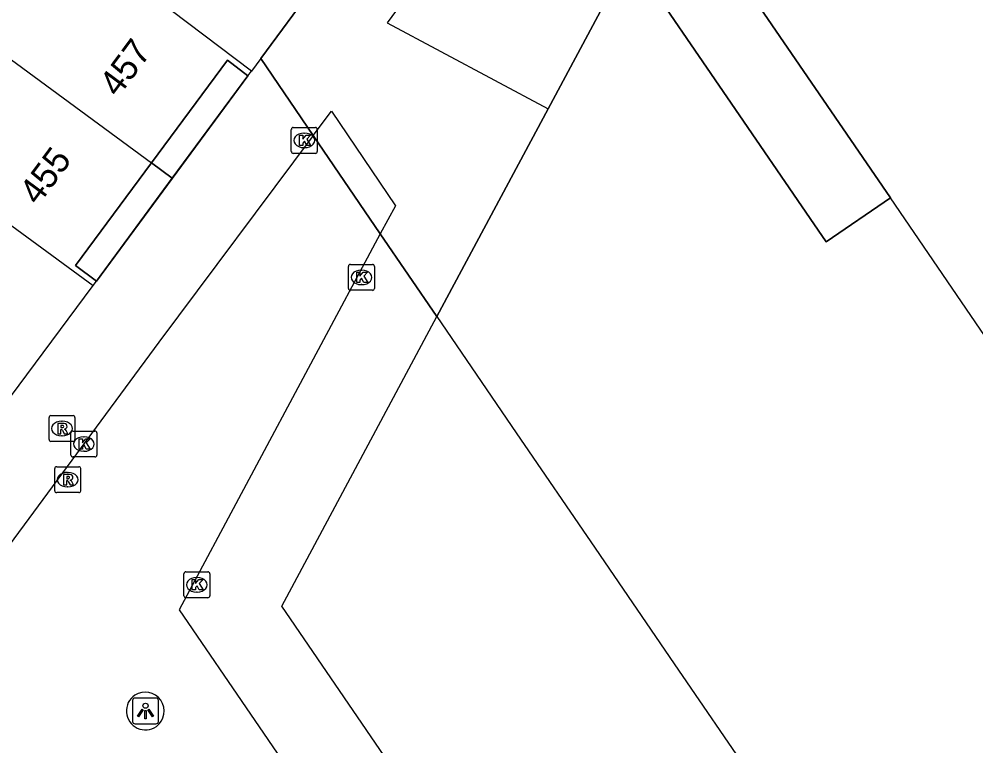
# Model space of a CAD drawing. Extents: x 155275 to 156263, y 382654 to 383635.
# Drawn here: x 155805.74 to 155842.67, y 383296.5 to 383324.56 of the extents above; entities that cross this region are included whole.
import ezdxf

# ---------------------------------------------------------------- set-up
doc = ezdxf.new("R2010")
doc.units = 0
for name, color, linetype in [('IMGEO_Hek', 7, 'Continuous'), ('IMGEO_Kolk', 7, 'Continuous'), ('IMGEO_Lichtpunt', 7, 'Continuous'), ('IMGEO_Pand', 7, 'Continuous'), ('IMGEO_Pand_nummerreeks', 7, 'Continuous'), ('IMGEO_Pand_overbouw', 7, 'Continuous'), ('IMGEO_Rijbaan_lokaal_open', 7, 'Continuous'), ('IMGEO_Rioolput', 7, 'Continuous'), ('IMGEO_Voetpad_open', 7, 'Continuous')]:
    doc.layers.add(name, color=color, linetype=linetype)

msp = doc.modelspace()

# ---------------------------------------------------------------- linework, layer by layer
at = {"layer": 'IMGEO_Hek'}
msp.add_lwpolyline([(155875.206, 383215.094), (155815.878, 383301.895), (155821.855, 383313.072)], dxfattribs=at)
at = {"layer": 'IMGEO_Kolk'}
for p, q in [((155816.242, 383319.449), (155816.242, 383320.301)), ((155816.317, 383320.375), (155817.169, 383320.375)), ((155817.243, 383320.301), (155817.243, 383319.449)), ((155816.73, 383320.155), (155816.755, 383320.155)), ((155816.753, 383319.595), (155816.728, 383319.595)), ((155817.169, 383319.375), (155816.317, 383319.375)), ((155818.446, 383314.16), (155818.446, 383315.012)), ((155818.521, 383315.086), (155819.373, 383315.086)), ((155818.934, 383314.866), (155818.959, 383314.866)), ((155819.447, 383315.012), (155819.447, 383314.16)), ((155819.373, 383314.086), (155818.521, 383314.086)), ((155818.957, 383314.306), (155818.932, 383314.306)), ((155807.734, 383307.726), (155807.734, 383308.578)), ((155807.809, 383308.652), (155808.661, 383308.652)), ((155808.735, 383308.578), (155808.735, 383307.726)), ((155808.222, 383308.432), (155808.247, 383308.432)), ((155808.245, 383307.872), (155808.22, 383307.872)), ((155808.661, 383307.652), (155807.809, 383307.652)), ((155812.095, 383302.292), (155812.095, 383303.144)), ((155812.17, 383303.218), (155813.022, 383303.218)), ((155812.583, 383302.998), (155812.608, 383302.998)), ((155813.096, 383303.144), (155813.096, 383302.292)), ((155813.022, 383302.218), (155812.17, 383302.218)), ((155812.606, 383302.438), (155812.581, 383302.438))]:
    msp.add_line(p, q, dxfattribs=at)
for points in [[(155816.242, 383319.449), (155816.242, 383320.301)], [(155816.317, 383320.375), (155817.169, 383320.375)], [(155817.243, 383320.301), (155817.243, 383319.449)], [(155816.563, 383320.075), (155816.686, 383320.075), (155816.686, 383319.924), (155816.816, 383320.075), (155816.98, 383320.075), (155816.834, 383319.924), (155816.987, 383319.675), (155816.835, 383319.675), (155816.75, 383319.839), (155816.686, 383319.772), (155816.686, 383319.675), (155816.563, 383319.675), (155816.563, 383320.075)], [(155817.169, 383319.375), (155816.317, 383319.375)], [(155818.446, 383314.16), (155818.446, 383315.012)], [(155818.521, 383315.086), (155819.373, 383315.086)], [(155818.767, 383314.786), (155818.89, 383314.786), (155818.89, 383314.635), (155819.02, 383314.786), (155819.184, 383314.786), (155819.038, 383314.635), (155819.191, 383314.386), (155819.039, 383314.386), (155818.954, 383314.55), (155818.89, 383314.483), (155818.89, 383314.386), (155818.767, 383314.386), (155818.767, 383314.786)], [(155819.447, 383315.012), (155819.447, 383314.16)], [(155819.373, 383314.086), (155818.521, 383314.086)], [(155807.734, 383307.726), (155807.734, 383308.578)], [(155807.809, 383308.652), (155808.661, 383308.652)], [(155808.735, 383308.578), (155808.735, 383307.726)], [(155808.055, 383308.352), (155808.178, 383308.352), (155808.178, 383308.201), (155808.308, 383308.352), (155808.472, 383308.352), (155808.326, 383308.201), (155808.479, 383307.952), (155808.327, 383307.952), (155808.242, 383308.116), (155808.178, 383308.049), (155808.178, 383307.952), (155808.055, 383307.952), (155808.055, 383308.352)], [(155808.661, 383307.652), (155807.809, 383307.652)], [(155812.095, 383302.292), (155812.095, 383303.144)], [(155812.17, 383303.218), (155813.022, 383303.218)], [(155813.096, 383303.144), (155813.096, 383302.292)], [(155812.416, 383302.918), (155812.539, 383302.918), (155812.539, 383302.767), (155812.669, 383302.918), (155812.833, 383302.918), (155812.687, 383302.767), (155812.84, 383302.518), (155812.688, 383302.518), (155812.603, 383302.682), (155812.539, 383302.615), (155812.539, 383302.518), (155812.416, 383302.518), (155812.416, 383302.918)], [(155813.022, 383302.218), (155812.17, 383302.218)]]:
    msp.add_lwpolyline(points, dxfattribs=at)
for centre, start, end in [((155816.319, 383320.299), 91.552, 178.448), ((155816.319, 383320.299), 91.552, 178.448), ((155817.167, 383320.299), 1.552, 88.448), ((155817.167, 383320.299), 1.552, 88.448), ((155816.319, 383319.451), 181.552, 268.448), ((155816.319, 383319.451), 181.552, 268.448), ((155817.167, 383319.451), 271.552, 358.448), ((155817.167, 383319.451), 271.552, 358.448), ((155818.523, 383315.01), 91.552, 178.448), ((155818.523, 383315.01), 91.552, 178.448), ((155819.371, 383315.01), 1.552, 88.448), ((155819.371, 383315.01), 1.552, 88.448), ((155818.523, 383314.162), 181.552, 268.448), ((155818.523, 383314.162), 181.552, 268.448), ((155819.371, 383314.162), 271.552, 358.448), ((155819.371, 383314.162), 271.552, 358.448), ((155807.811, 383308.576), 91.552, 178.448), ((155807.811, 383308.576), 91.552, 178.448), ((155808.659, 383308.576), 1.552, 88.448), ((155808.659, 383308.576), 1.552, 88.448), ((155807.811, 383307.728), 181.552, 268.448), ((155807.811, 383307.728), 181.552, 268.448), ((155808.659, 383307.728), 271.552, 358.448), ((155808.659, 383307.728), 271.552, 358.448), ((155812.172, 383303.142), 91.552, 178.448), ((155812.172, 383303.142), 91.552, 178.448), ((155813.02, 383303.142), 1.552, 88.448), ((155813.02, 383303.142), 1.552, 88.448), ((155812.172, 383302.294), 181.552, 268.448), ((155812.172, 383302.294), 181.552, 268.448), ((155813.02, 383302.294), 271.552, 358.448), ((155813.02, 383302.294), 271.552, 358.448)]:
    msp.add_arc(centre, 0.0765, start, end, dxfattribs=at)
for centre, major_axis, ratio, start_param, end_param in [((155816.729, 383319.875), (-0.387, 0.002), 0.722429, 4.712389, 7.853982), ((155816.754, 383319.875), (-0.39, 0.002), 0.717154, 1.570796, 4.712389), ((155818.933, 383314.586), (-0.387, 0.002), 0.722429, 4.712389, 7.853982), ((155818.958, 383314.586), (-0.39, 0.002), 0.717154, 1.570796, 4.712389), ((155808.221, 383308.152), (-0.387, 0.002), 0.722429, 4.712389, 7.853982), ((155808.246, 383308.152), (-0.39, 0.002), 0.717154, 1.570796, 4.712389), ((155812.582, 383302.718), (-0.387, 0.002), 0.722429, 4.712389, 7.853982), ((155812.607, 383302.718), (-0.39, 0.002), 0.717154, 1.570796, 4.712389)]:
    msp.add_ellipse(centre, major_axis=major_axis, ratio=ratio, start_param=start_param, end_param=end_param, dxfattribs=at)
at = {"layer": 'IMGEO_Lichtpunt'}
for p, q in [((155810.116, 383298.25), (155810.116, 383297.443)), ((155810.116, 383298.25), (155810.116, 383297.443)), ((155811.018, 383298.345), (155810.21, 383298.345)), ((155811.018, 383298.345), (155810.21, 383298.345)), ((155811.112, 383297.443), (155811.112, 383298.25)), ((155811.112, 383297.443), (155811.112, 383298.25)), ((155810.21, 383297.349), (155811.018, 383297.349)), ((155810.21, 383297.349), (155811.018, 383297.349))]:
    msp.add_line(p, q, dxfattribs=at)
for points in [[(155810.49, 383297.914), (155810.529, 383297.886), (155810.341, 383297.624), (155810.303, 383297.651), (155810.49, 383297.914)], [(155810.592, 383297.866), (155810.639, 383297.866), (155810.639, 383297.544), (155810.592, 383297.544), (155810.592, 383297.866)], [(155810.702, 383297.886), (155810.74, 383297.913), (155810.927, 383297.651), (155810.888, 383297.623), (155810.702, 383297.886)]]:
    msp.add_lwpolyline(points, dxfattribs=at)
msp.add_circle((155810.615, 383298.048), 0.0994, dxfattribs=at)
for centre, start, end in [((155810.21, 383298.25), 90, 180), ((155810.21, 383298.25), 90, 180), ((155811.018, 383298.25), 0, 90), ((155811.018, 383298.25), 0, 90), ((155810.21, 383297.443), 180, 270), ((155810.21, 383297.443), 180, 270), ((155811.018, 383297.443), 270, 0), ((155811.018, 383297.443), 270, 360)]:
    msp.add_arc(centre, 0.0946, start, end, dxfattribs=at)
at = {"layer": 'IMGEO_Pand'}
for points in [[(155814.704, 383322.549), (155806.716, 383328.599)], [(155815.059, 383323.031), (155819.212, 383328.662)], [(155839.367, 383317.662), (155836.881, 383315.962), (155836.27, 383316.857), (155833.221, 383321.318), (155829.325, 383327.019), (155826.154, 383321.097)], [(155803.581, 383324.349), (155810.843, 383319.005)], [(155810.843, 383319.005), (155813.774, 383322.971), (155814.565, 383322.361)], [(155815.059, 383323.031), (155814.704, 383322.549)], [(155814.565, 383322.361), (155814.704, 383322.549)], [(155826.154, 383321.097), (155821.855, 383313.072)], [(155800.509, 383320.186), (155808.587, 383314.27)], [(155808.716, 383314.444), (155807.912, 383315.039), (155810.843, 383319.005)], [(155858.063, 383290.277), (155856.982, 383291.861), (155853.935, 383296.324), (155850.889, 383300.785), (155847.843, 383305.247), (155844.797, 383309.709), (155841.751, 383314.171), (155839.367, 383317.662)], [(155808.587, 383314.27), (155808.716, 383314.444)], [(155805.407, 383309.97), (155808.587, 383314.27)], [(155821.855, 383313.072), (155824.923, 383308.587), (155827.973, 383304.128), (155831.023, 383299.669), (155834.073, 383295.21), (155837.123, 383290.751), (155840.173, 383286.292), (155843.223, 383281.833), (155846.273, 383277.374), (155847.799, 383275.144), (155850.849, 383270.685), (155853.899, 383266.226), (155856.949, 383261.767), (155859.999, 383257.308), (155863.049, 383252.849), (155866.099, 383248.39), (155869.149, 383243.931), (155872.199, 383239.472), (155875.249, 383235.013), (155878.299, 383230.554), (155881.349, 383226.094), (155884.399, 383221.636), (155887.087, 383217.706)]]:
    msp.add_lwpolyline(points, dxfattribs=at)
at = {"layer": 'IMGEO_Pand_overbouw'}
for points in [[(155821.855, 383313.072), (155826.154, 383321.097), (155829.325, 383327.019), (155833.221, 383321.318), (155836.27, 383316.857), (155836.881, 383315.962), (155839.367, 383317.662), (155833.414, 383326.361), (155825.752, 383337.528), (155823.869, 383334.975), (155822.317, 383332.871), (155819.212, 383328.662), (155815.059, 383323.031), (155817.087, 383320.059), (155819.677, 383316.264)], [(155810.843, 383319.005), (155811.648, 383318.413), (155814.565, 383322.361), (155813.774, 383322.971)], [(155808.716, 383314.444), (155811.648, 383318.413), (155810.843, 383319.005), (155807.912, 383315.039)]]:
    msp.add_lwpolyline(points, close=True, dxfattribs=at)
at = {"layer": 'IMGEO_Rijbaan_lokaal_open'}
for points in [[(155817.087, 383320.059), (155817.796, 383321.009), (155820.258, 383317.35), (155819.677, 383316.264)], [(155817.087, 383320.059), (155811.131, 383312.082), (155798.256, 383294.644), (155789.533, 383282.828), (155777.762, 383266.885), (155770.477, 383257.018), (155750.942, 383230.559), (155753.136, 383227.355), (155767.095, 383206.967), (155771.224, 383200.936), (155773.915, 383197.049), (155790.895, 383199.943), (155792.328, 383200.159), (155792.43, 383196.787)], [(155819.677, 383316.264), (155817.087, 383320.059)], [(155819.677, 383316.264), (155811.913, 383301.75), (155829.44, 383276.11), (155849.638, 383246.563), (155871.364, 383214.781)]]:
    msp.add_lwpolyline(points, dxfattribs=at)
for centre, start, end in [((155810.599, 383297.84), 306.1685, 122.9651), ((155810.61, 383297.847), 124.0068, 305.1268)]:
    msp.add_arc(centre, 0.734, start, end, dxfattribs=at)
at = {"layer": 'IMGEO_Rioolput'}
for p, q in [((155806.963, 383309.25), (155807.815, 383309.25)), ((155806.888, 383308.324), (155806.888, 383309.176)), ((155807.376, 383309.03), (155807.401, 383309.03)), ((155807.889, 383309.176), (155807.889, 383308.324)), ((155807.399, 383308.47), (155807.374, 383308.47)), ((155807.815, 383308.25), (155806.963, 383308.25)), ((155807.109, 383306.35), (155807.109, 383307.202)), ((155807.184, 383307.276), (155808.036, 383307.276)), ((155807.597, 383307.056), (155807.622, 383307.056)), ((155808.11, 383307.202), (155808.11, 383306.35)), ((155808.036, 383306.276), (155807.184, 383306.276)), ((155807.62, 383306.496), (155807.595, 383306.496))]:
    msp.add_line(p, q, dxfattribs=at)
for points in [[(155806.963, 383309.25), (155807.815, 383309.25)], [(155806.888, 383308.324), (155806.888, 383309.176)], [(155807.477, 383308.948), (155807.225, 383308.95), (155807.225, 383308.55)], [(155807.403, 383308.869), (155807.349, 383308.869), (155807.349, 383308.788)], [(155807.889, 383309.176), (155807.889, 383308.324)], [(155807.225, 383308.55), (155807.349, 383308.55), (155807.349, 383308.712), (155807.36, 383308.712)], [(155807.349, 383308.788), (155807.401, 383308.788)], [(155807.407, 383308.683), (155807.478, 383308.55), (155807.618, 383308.55), (155807.553, 383308.676)], [(155807.815, 383308.25), (155806.963, 383308.25)], [(155807.109, 383306.35), (155807.109, 383307.202)], [(155807.184, 383307.276), (155808.036, 383307.276)], [(155808.11, 383307.202), (155808.11, 383306.35)], [(155807.698, 383306.974), (155807.446, 383306.976), (155807.446, 383306.576)], [(155807.446, 383306.576), (155807.57, 383306.576), (155807.57, 383306.738), (155807.581, 383306.738)], [(155807.624, 383306.895), (155807.57, 383306.895), (155807.57, 383306.814)], [(155807.57, 383306.814), (155807.622, 383306.814)], [(155807.628, 383306.709), (155807.699, 383306.576), (155807.839, 383306.576), (155807.774, 383306.702)], [(155808.036, 383306.276), (155807.184, 383306.276)]]:
    msp.add_lwpolyline(points, dxfattribs=at)
for centre, radius, start, end in [((155806.965, 383309.174), 0.0765, 91.552, 178.448), ((155806.965, 383309.174), 0.0765, 91.552, 178.448), ((155807.813, 383309.174), 0.0765, 1.552, 88.448), ((155807.813, 383309.174), 0.0765, 1.552, 88.448), ((155807.409, 383308.773), 0.0964, 77.0061, 93.1865), ((155807.423, 383308.83), 0.0378, 276.6634, 79.6772), ((155807.476, 383308.838), 0.109, 350.3612, 89.416), ((155807.359, 383308.659), 0.0533, 26.0293, 88.6989), ((155807.385, 383308.977), 0.19, 274.7715, 282.9687), ((155807.474, 383308.838), 0.112, 277.5842, 350.9817), ((155807.458, 383308.623), 0.108, 29.5134, 73.7905), ((155806.965, 383308.326), 0.0765, 181.552, 268.448), ((155806.965, 383308.326), 0.0765, 181.552, 268.448), ((155807.813, 383308.326), 0.0765, 271.552, 358.448), ((155807.813, 383308.326), 0.0765, 271.552, 358.448), ((155807.186, 383307.2), 0.0765, 91.552, 178.448), ((155807.186, 383307.2), 0.0765, 91.552, 178.448), ((155808.034, 383307.2), 0.0765, 1.552, 88.448), ((155808.034, 383307.2), 0.0765, 1.552, 88.448), ((155807.58, 383306.685), 0.0533, 26.0293, 88.6989), ((155807.606, 383307.003), 0.19, 274.7715, 282.9687), ((155807.63, 383306.799), 0.0964, 77.0061, 93.1865), ((155807.644, 383306.856), 0.0378, 276.6634, 79.6772), ((155807.697, 383306.864), 0.109, 350.3612, 89.416), ((155807.695, 383306.864), 0.112, 277.5842, 350.9817), ((155807.679, 383306.649), 0.108, 29.5134, 73.7905), ((155807.186, 383306.352), 0.0765, 181.552, 268.448), ((155807.186, 383306.352), 0.0765, 181.552, 268.448), ((155808.034, 383306.352), 0.0765, 271.552, 358.448), ((155808.034, 383306.352), 0.0765, 271.552, 358.448)]:
    msp.add_arc(centre, radius, start, end, dxfattribs=at)
for centre, major_axis, ratio, start_param, end_param in [((155807.375, 383308.75), (-0.387, 0.002), 0.722429, 4.712389, 7.853982), ((155807.4, 383308.75), (-0.39, 0.002), 0.717154, 1.570796, 4.712389), ((155807.596, 383306.776), (-0.387, 0.002), 0.722429, 4.712389, 7.853982), ((155807.621, 383306.776), (-0.39, 0.002), 0.717154, 1.570796, 4.712389)]:
    msp.add_ellipse(centre, major_axis=major_axis, ratio=ratio, start_param=start_param, end_param=end_param, dxfattribs=at)
at = {"layer": 'IMGEO_Voetpad_open'}
for points in [[(155827.631, 383334.79), (155833.414, 383326.361), (155839.367, 383317.662)], [(155827.022, 383334.026), (155819.943, 383324.409), (155826.154, 383321.097)], [(155817.087, 383320.059), (155815.059, 383323.031)], [(155814.565, 383322.361), (155808.716, 383314.444)], [(155821.855, 383313.072), (155819.677, 383316.264)], [(155875.206, 383215.094), (155815.878, 383301.895), (155821.855, 383313.072)]]:
    msp.add_lwpolyline(points, dxfattribs=at)

# ---------------------------------------------------------------- texts
at = {"layer": 'IMGEO_Pand_nummerreeks'}
for s, p in [('457', (155809.556, 383321.502)), ('455', (155806.47, 383317.327))]:
    msp.add_text(s, height=1, rotation=53.5352, dxfattribs=at).set_placement(p)

doc.saveas('drawing.dxf')
